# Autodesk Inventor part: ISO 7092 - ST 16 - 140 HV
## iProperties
Created: 2009-02
Part Number: ISO 7092 - ST 16 - 140 HV
Material: Stainless Steel
Description: Plain washers-Small series-Product grade A
Document SubType Name: Modeling
Standard: ISO 7092
Designer: 904Chiaki
Standard Revision: Second edition 2000-06-01
Standards Organization: ISO
Language: en-US
Size Designation: ST 16 - 140 HV
Categories: <MemberInstance><Categories><Category DisplayName="Fasteners" InternalName="e4da775c-781d-43d5-af7c-5136215cf5a6" Mnemonic="FSTN"><Category DisplayName="Washers
Density: 8.08 g/cm^3
Mass: 7.8532 g
Surface Area: 11.3097 cm^2
Volume: 0.97193 cm^3
IsCustomPart: 0
Author: 904Chiaki
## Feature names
1. Body [Extrusion]
